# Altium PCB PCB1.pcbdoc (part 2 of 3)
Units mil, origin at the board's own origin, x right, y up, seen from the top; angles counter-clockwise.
Board outline 8664.15 x 6684.89 mil, 2 copper layers (Top Layer, Bottom Layer); 317 components, 306 nets, 1008 pads, 181 vias.
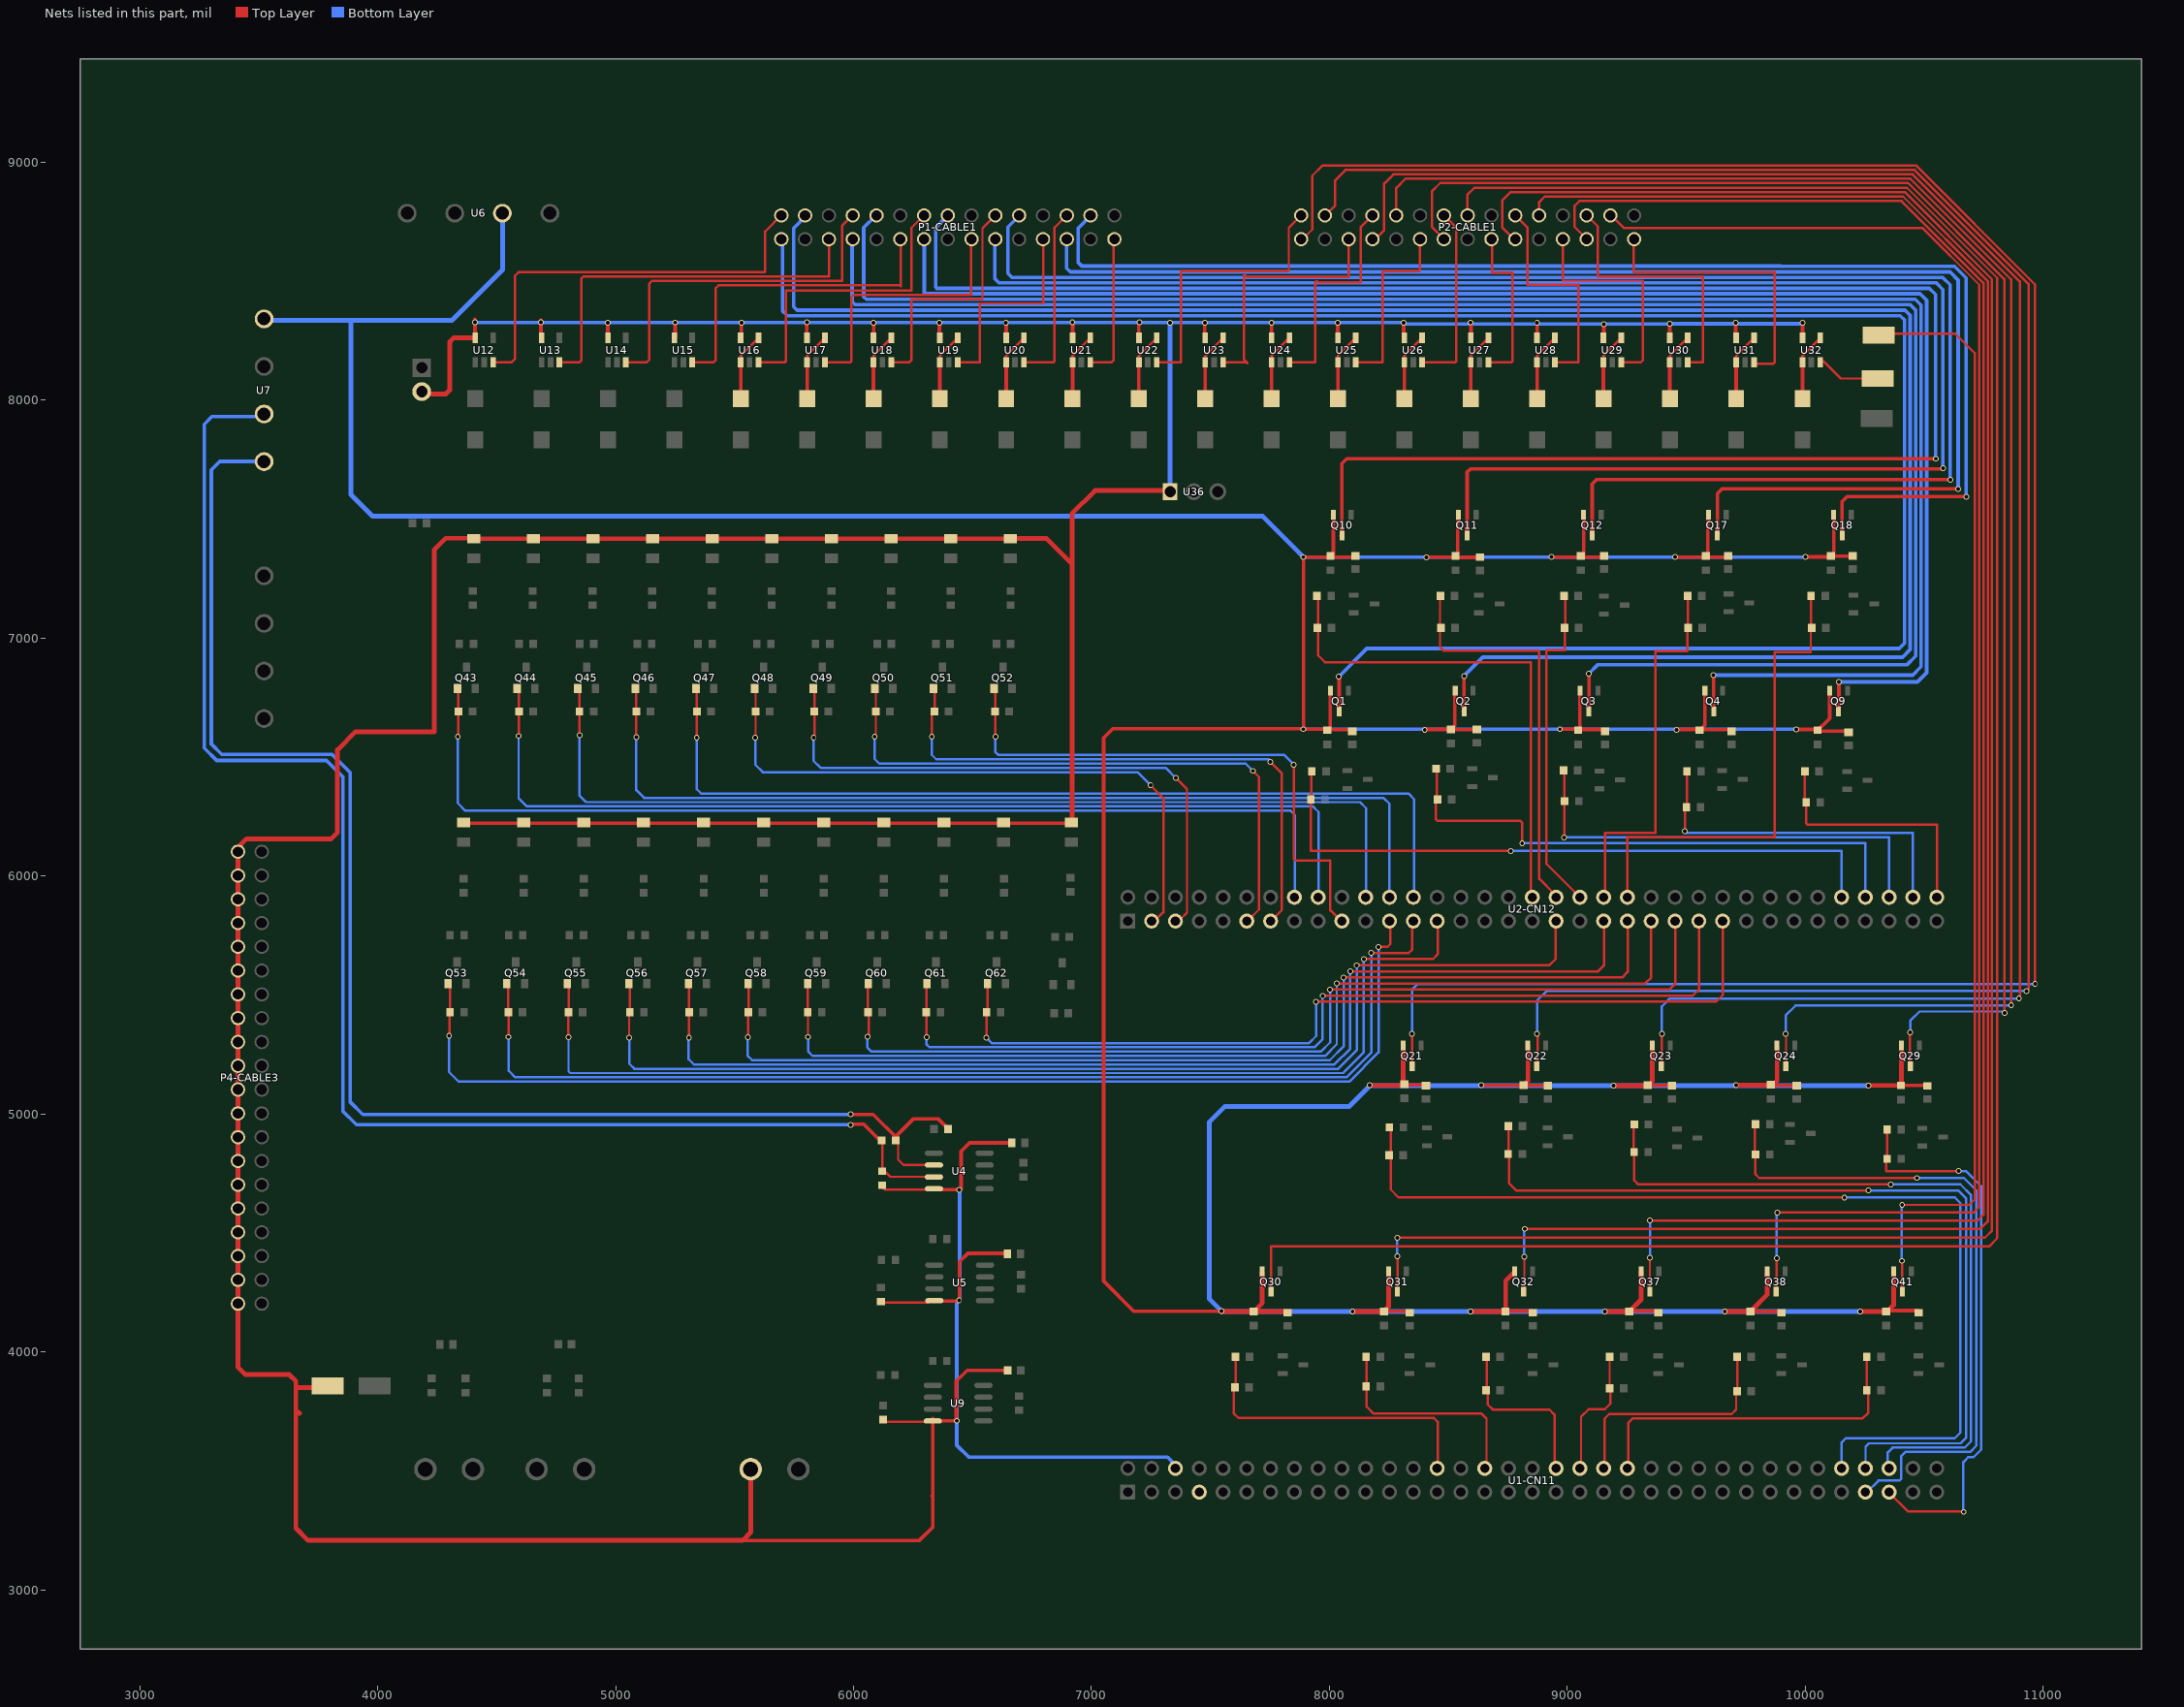
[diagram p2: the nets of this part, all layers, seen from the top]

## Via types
v1: diameter 24.02, hole 16, Top Layer to Bottom Layer, 181 vias

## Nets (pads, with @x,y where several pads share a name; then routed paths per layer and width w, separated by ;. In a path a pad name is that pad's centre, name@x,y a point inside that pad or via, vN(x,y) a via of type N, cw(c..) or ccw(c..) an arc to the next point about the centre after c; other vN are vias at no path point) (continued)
$9N2849: D5.2 U16.1 U16.4 | length 287.2
  Top Layer w10: U16.1@5526.13,8160.48 5526.13,8187.13 5600.93,8261.93 U16.4@5600.93,8262.85
  Top Layer w15: U16.1@5526.13,8160.48 5526.13,8006.71 D5.2@5526.2,8006.64
$9N2931: D6.2 U17.1 U17.4 | length 287.2
  Top Layer w10: U17.1@5805.07,8160.48 5805.07,8187.13 5879.87,8261.93 U17.4@5879.87,8262.85
  Top Layer w15: U17.1@5805.07,8160.48 5805.14,8160.4 D6.2@5805.14,8006.64
$9N3779: D12.2 U23.1 U23.4 | length 287.2
  Top Layer w10: U23.1@7478.69,8160.48 7478.69,8187.13 7553.49,8261.93 U23.4@7553.49,8262.85
  Top Layer w15: U23.1@7478.69,8160.48 7478.69,8006.71 D12.2@7478.76,8006.64
$9N3789: D11.2 U22.1 U22.4 | length 287.2
  Top Layer w10: U22.1@7199.75,8160.48 7199.75,8188.05 U22.4@7274.55,8262.85
  Top Layer w15: U22.1@7199.75,8160.48 7199.75,8006.71 D11.2@7199.83,8006.64
$9N3799: D10.2 U21.1 U21.4 | length 287.2
  Top Layer w10: U21.1@6920.82,8160.48 6920.82,8188.05 U21.4@6995.62,8262.85
  Top Layer w15: U21.1@6920.82,8160.48 6920.82,8006.71 D10.2@6920.89,8006.64
$9N3809: D9.2 U20.1 U20.4 | length 287.2
  Top Layer w10: U20.1@6641.88,8160.48 6641.88,8187.13 6716.68,8261.93 U20.4@6716.68,8262.85
  Top Layer w15: U20.1@6641.88,8160.48 6641.88,8006.71 D9.2@6641.95,8006.64
$9N3819: D8.2 U19.1 U19.4 | length 287.2
  Top Layer w10: U19.1@6362.94,8160.48 6362.94,8187.13 6437.74,8261.93 U19.4@6437.74,8262.85
  Top Layer w15: U19.1@6362.94,8160.48 6362.94,8006.71 D8.2@6363.02,8006.64
$9N3829: D7.2 U18.1 U18.4 | length 287.2
  Top Layer w10: U18.1@6084,8160.48 6084,8187.13 6158.8,8261.93 U18.4@6158.8,8262.85
  Top Layer w15: U18.1@6084,8160.48 6084,8006.71 D7.2@6084.08,8006.64
$10N643: D18.2 U29.1 U29.4 | length 287.2
  Top Layer w10: U29.1@9152.31,8160.48 9152.31,8188.05 U29.4@9227.11,8262.85
  Top Layer w15: U29.1@9152.31,8160.48 9152.31,8006.71 D18.2@9152.39,8006.64
$10N647: D17.2 U28.1 U28.4 | length 287.2
  Top Layer w10: U28.1@8873.38,8160.48 8873.38,8187.13 8948.18,8261.93 U28.4@8948.18,8262.85
  Top Layer w15: U28.1@8873.38,8160.48 8873.38,8006.71 D17.2@8873.45,8006.64
$10N651: D16.2 U27.1 U27.4 | length 287.2
  Top Layer w10: U27.1@8594.44,8160.48 8594.44,8188.05 U27.4@8669.24,8262.85
  Top Layer w15: U27.1@8594.44,8160.48 8594.44,8006.71 D16.2@8594.51,8006.64
$10N655: D15.2 U26.1 U26.4 | length 287.2
  Top Layer w10: U26.1@8315.5,8160.48 8315.5,8188.05 U26.4@8390.3,8262.85
  Top Layer w15: U26.1@8315.5,8160.48 8315.58,8160.4 D15.2@8315.58,8006.64
$10N659: D14.2 U25.1 U25.4 | length 287.2
  Top Layer w10: U25.1@8036.56,8160.48 8036.56,8188.05 U25.4@8111.36,8262.85
  Top Layer w15: U25.1@8036.56,8160.48 8036.64,8160.4 D14.2@8036.64,8006.64
$10N663: D13.2 U24.1 U24.4 | length 287.2
  Top Layer w10: U24.1@7757.63,8160.48 7757.63,8188.05 U24.4@7832.43,8262.85
  Top Layer w15: U24.1@7757.63,8160.48 7757.7,8160.4 D13.2@7757.7,8006.64
$10N673: D21.2 U32.1 U32.4 | length 287.2
  Top Layer w10: U32.1@9989.12,8160.48 9989.12,8187.13 10063.92,8261.93 U32.4@10063.92,8262.85
  Top Layer w15: U32.1@9989.12,8160.48 9989.12,8006.71 D21.2@9989.2,8006.64
$10N677: D20.2 U31.1 U31.4 | length 287.2
  Top Layer w10: U31.1@9710.19,8160.48 9710.19,8187.13 9784.99,8261.93 U31.4@9784.99,8262.85
  Top Layer w15: U31.1@9710.19,8160.48 9710.19,8006.71 D20.2@9710.26,8006.64
$10N681: D19.2 U30.1 U30.4 | length 287.2
  Top Layer w10: U30.1@9431.25,8160.48 9431.25,8188.05 U30.4@9506.05,8262.85
  Top Layer w15: U30.1@9431.25,8160.48 9431.25,8006.71 D19.2@9431.32,8006.64
+5V: C22.1 C23.1 C24.1 CN4.1 LED1.1 LED2.1 LED3.1 LED4.1 LED5.1 LED6.1 LED7.1 LED8.1 LED9.1 LED10.1 LED11.1 LED12.1 LED13.1 LED14.1 LED15.1 LED16.1 LED17.1 LED18.1 LED19.1 LED20.1 LED21.1 P4-CABLE3.1 P4-CABLE3.3 P4-CABLE3.5 P4-CABLE3.7 P4-CABLE3.9 P4-CABLE3.11 P4-CABLE3.13 P4-CABLE3.15 P4-CABLE3.17 P4-CABLE3.19 P4-CABLE3.21 P4-CABLE3.23 P4-CABLE3.25 P4-CABLE3.27 P4-CABLE3.29 P4-CABLE3.31 P4-CABLE3.33 P4-CABLE3.35 P4-CABLE3.37 P4-CABLE3.39 R127.2 R128.2 R135.2 U1-CN11.6 U3.1 U4.8 U5.8 U9.8 U12.5 U13.5 U14.5 U15.5 U16.5 U17.5 U18.5 U19.5 U20.5 U21.5 U22.5 U23.5 U24.5 U25.5 U26.5 U27.5 U28.5 U29.5 U30.5 U31.5 U32.5 U33.2 U36.1 | length 27940.9
  Top Layer w10: R128.2@6112.68,4207.73 6316.98,4207.73 U5.8@6322.09,4212.84 ; R135.2@6122.56,3705.82 6323.67,3705.82 U9.8@6331.33,3713.48 ; R127.2@6124.77,4689.2 6131.79,4682.17 6339.38,4682.17 U4.8@6346.3,4682.31
  Top Layer w15: LED11.1@4357.05,6228.39 4362.71,6222.72 LED21.1@6919.04,6222.72 ; 4408.55,8340.28 4409.19,8339.64 U12.5@4409.19,8260.19 ; U13.5@4686.01,8261.47 v1@4686.01,8335.8 ; LED3.1@4905.51,7418.36 LED3.1@4906.66,7419.51 ; U14.5@4967.31,8263.39 v1@4967.31,8328.75 ; LED4.1@5156.04,7418.36 LED4.1@5157.53,7419.85 ; v1@5249.25,8327.47 5250.54,8326.19 U15.5@5250.54,8262.75 ; LED5.1@5406.56,7418.36 LED5.1@5411.28,7423.08 ; U16.5@5526.07,8265.95 5528.64,8268.52 v1@5528.64,8323.62 ; 5534.4,3207.72 6277.76,3207.72 6333.01,3262.97 6333.01,3393.94 ; v1@5802.89,8317.22 5804.17,8315.93 U17.5@5804.17,8264.67 ; U18.5@6084.19,8263.39 6084.19,8315.29 v1@6086.12,8317.22 ; 6330.57,3393.94 6333.01,3393.94 ; U9.8@6333.01,3719.3 6333.01,3393.94 ; U9.8@6336.78,3710.39 6432.54,3710.39 6432.54,3877.03 6478.19,3922.68 C24.1@6641.31,3922.68 ; U4.8@6339.38,4682.17 U4.8@6339.38,4683.15 ; U5.8@6340.17,4212.83 6341.02,4213.69 v1@6444.66,4213.69 ; U4.8@6341.53,4682.31 6346.3,4682.31 6450.06,4682.31 6452.61,4684.86 6452.61,4843.51 6488.05,4878.95 C22.1@6664.58,4878.95 ; U19.5@6361.01,8262.75 6361.01,8309.53 6363.58,8312.09 ; v1@6443.57,4213.78 6445.08,4215.3 6445.08,4378.19 6481.05,4414.16 6640.23,4414.16 C23.1@6644.06,4410.32 ; v1@6640.69,8327.75 6641.68,8326.76 U20.5@6641.68,8262.75 ; U21.5@6921.06,8263.39 6921.06,8311.45 6923.62,8314.01 ; U22.5@7199.8,8263.39 7199.8,8315.29 v1@7201.72,8317.22 ; U23.5@7475.98,8261.47 7475.98,8322.34 v1@7477.9,8324.26 ; U24.5@7757.92,8260.83 7757.92,8320.42 v1@7758.56,8321.06 ; U25.5@8035.38,8263.39 8035.38,8315.29 v1@8039.86,8319.78 ; U26.5@8312.84,8265.31 v1@8312.84,8319.78 ; U27.5@8595.42,8262.75 8595.42,8318.5 v1@8597.35,8320.42 ; v1@8872.88,8319.78 8874.16,8318.5 U28.5@8874.16,8264.03 ; U29.5@9153.54,8263.39 9153.8,8263.64 9153.8,8318.89 v1@9153.54,8319.14 ; v1@9430.15,8317 9431,8316.15 U30.5@9431,8262.11 ; U31.5@9708.46,8265.31 9708.46,8320.42 v1@9709.1,8321.06 ; v1@9989.01,8322.46 9989.01,8264.15 U32.5@9989.77,8263.39
  Top Layer w20: P4-CABLE3.1@3412.35,6102 3412.35,3936.07 3443.84,3904.57 3628.88,3904.57 3656.44,3877.01 3656.44,3849.59 ; P4-CABLE3.1@3412.8,6099.44 3413.45,6100.08 3413.45,6121.3 3448.6,6156.46 3804.33,6156.46 3830.85,6182.98 3830.85,6530.56 3907.38,6607.09 4237.28,6607.09 4237.28,7371.71 4285.76,7420.19 LED1.1@4402.64,7420.19 ; 3667.07,3746.51 3671,3742.57 ; CN4.1@3790.3,3857.33 3782.56,3849.59 3656.44,3849.59 ; U33.2@4183.36,8026.42 4286.3,8026.42 4303.02,8043.14 4303.02,8245.86 4319.23,8262.08 U12.5@4404.72,8262.08 ; LED1.1@4400.54,7422.29 LED1.1@4402.64,7420.19 ; U3.1@5568.25,3506.93 5568.25,3241.58 5534.4,3207.72 3707.62,3207.72 3656.44,3258.9 3656.44,3727.41 3656.44,3849.59 ; LED10.1@6654.41,7419.88 6655.45,7418.84 6812.26,7418.84 6918.73,7312.37 ; LED10.1@6659.19,7418.36 LED9.1@6408.66,7418.36 LED8.1@6158.14,7418.36 LED7.1@5907.61,7418.36 LED6.1@5657.09,7418.36 LED5.1@5406.56,7418.36 LED4.1@5156.04,7418.36 LED3.1@4905.51,7418.36 LED2.1@4654.99,7418.36 LED1.1@4404.46,7418.36 LED1.1@4402.64,7420.19 ; LED21.1@6922.53,6222.08 6919.03,6225.59 6919.03,7312.08 ; U36.1@7327.32,7620.59 7015.61,7620.59 6918.73,7523.71 6918.73,7312.37 ; 6918.73,7312.37 6919.03,7312.08 ; 6918.73,7312.37 6919.03,7312.08
  Bottom Layer w15: v1@4408.63,8328.43 4410.55,8326.51 v1(4966.64,8326.51) v1(6084.6,8326.51) v1(6360.99,8326.51) v1(6640.79,8326.51) v1(8035.57,8326.51) v1(8312.81,8326.51) 8318.48,8320.84 9429.23,8320.84 v1(9430.34,8321.95) 9984.65,8321.95 v1(9989.21,8326.51) ; v1@6446.44,4679.39 6446.44,4219.89 v1(6443.57,4217.02) 6434.46,4207.91 v1(6434.46,3710.39) 6434.46,3607.66 6484.86,3557.25 7320.03,3557.25 7349.26,3528.02 U1-CN11.6@7349.26,3512.25
  Bottom Layer w20: v1(7331.35,8325.78) 7331.35,7623.82 U36.1@7342.85,7612.33
  other v1: 6444.37,4681.36 9154.78,8319.77 5529.25,8325.65 7476.8,8326.08 7757.47,8325.65 8873.71,8326.08 9708.86,8325.65 4686.41,8327.36 5250.72,8326.93 5803.93,8327.36 8594.33,8326.93 4409.59,8327.79 6920.18,8328.22 7202.12,8327.79
AM1-: C1.1 C2.1 C3.1 C4.1 C5.1 C6.1 C7.1 C8.1 C9.1 C10.1 C11.1 C12.1 C13.1 C14.1 C15.1 C16.1 C17.1 C18.1 C19.1 C20.1 C21.1 Q1.2 Q2.2 Q3.2 Q4.2 Q9.2 Q10.2 Q11.2 Q12.2 Q17.2 Q18.2 Q21.2 Q22.2 Q23.2 Q24.2 Q29.2 Q30.2 Q31.2 Q32.2 Q37.2 Q38.2 Q41.2 R1.2 R2.2 R3.2 R4.2 R13.2 R14.2 R15.2 R16.2 R25.2 R26.2 R31.2 R32.2 R33.2 R34.2 R43.2 R44.2 R45.2 R46.2 R55.2 R56.2 R61.2 U6.3 U7.4 | length 29666.8
  Top Layer w10: R44.2@7676.44,4163.63 R44.2@7682.21,4169.39 ; C11.1@8419.23,5126.41 C11.1@8421.15,5124.49 ; R2.2@8509.36,6614.09 8516.96,6621.7 R2.2@8515.94,6621.7 ; R3.2@9045.17,6608.18 R3.2@9053.71,6616.73 ; R16.2@9051.67,7345.37 9061.28,7345.37 R16.2@9057.44,7341.52 ; R4.2@9554.71,6610.89 R4.2@9560.48,6616.65 ; R56.2@9770.15,4170.3 R56.2@9773.79,4173.95 ; R34.2@9851.42,5123.08 R34.2@9860.39,5123.08 ; R61.2@10336.6,4174.15 R61.2@10348.77,4174.15 ; R43.2@10405.25,5120.28 10405.25,5116.51 R43.2@10408.54,5113.23 ; R34.2@9860.39,5123.08 9862.96,5120.52 9865.52,5123.08 R34.2@9860.39,5123.08
  Top Layer w15: v1(7547.37,4171.17) 7178.28,4171.17 7051.55,4297.9 7051.55,6580.88 7090.41,6619.74 7889.05,6619.74 v1(7891.12,6617.67) ; v1(7891.62,7340.66) 7891.62,6618.17 v1(7891.12,6617.67) ; v1@7894.01,7340.64 R14.2@8000.38,7340.64 ; R1.2@7979.72,6619.47 7977.92,6617.67 v1(7891.12,6617.67) ; R1.2@8000.48,6615.56 8090.68,6615.56 C1.1@8096.24,6610 ; R1.2@8004.03,6619.1 Q1.2@8004.03,6778.02 ; R14.2@8006.55,7340.85 8112.07,7340.85 C6.1@8113.78,7342.55 ; R14.2@8006.55,7343.41 8017.23,7354.09 Q10.2@8017.23,7513.43 ; R45.2@8238.57,4170.35 8332.76,4170.35 C17.1@8337.25,4165.87 ; R31.2@8309,5122.18 8402.21,5122.18 C11.1@8402.85,5121.54 ; v1@8404.17,6616.57 8510.81,6616.57 8515.94,6621.7 8527.25,6633.01 Q2.2@8527.25,6775.27 ; v1@8414,7340.73 8525.22,7340.73 8540.22,7355.73 Q11.2@8540.22,7517.63 ; R2.2@8516.96,6621.7 8523.23,6615.43 C2.1@8624.63,6615.43 ; R15.2@8533.76,7347.17 8541.02,7339.91 C7.1@8633.29,7339.91 ; v1@8640.86,5120.29 8815.97,5120.29 8912.94,5120.29 C12.1@8916.36,5116.87 ; R46.2@8741.58,4171.48 8849.24,4171.48 C18.1@8856.28,4164.43 ; v1(8934.55,7341.15) 9049.04,7341.15 R16.2@9049.47,7341.58 ; v1@8971.23,6617.18 9045.56,6617.18 R3.2@9046.2,6616.54 ; Q3.2@9053.71,6781.62 9053.71,6616.73 9156.93,6616.73 C3.1@9166.22,6607.43 ; Q12.2@9069.93,7520.3 9069.93,7354.02 9061.28,7345.37 9065.84,7340.81 C8.1@9149.46,7340.81 ; R55.2@9270.55,4172.12 C19.1@9379.16,4172.12 ; R33.2@9343.28,5123.72 9347.11,5119.89 9432.36,5119.89 C13.1@9436.19,5123.72 ; v1(9453.16,7342.01) 9454.01,7341.15 R25.2@9578.33,7341.15 ; v1@9457.59,6613.34 9460.9,6616.65 R4.2@9560.48,6616.65 ; Q4.2@9578.74,6780.05 9578.74,6634.92 R4.2@9560.48,6616.65 ; R25.2@9582.45,7346.85 9591.1,7355.5 Q17.2@9591.1,7518.9 ; R25.2@9593.02,7346.85 9599.43,7340.44 C9.1@9678.25,7340.44 ; C4.1@9692.16,6605.12 9682.16,6615.12 9562.01,6615.12 R4.2@9560.48,6616.65 ; R56.2@9773.99,4169.66 9895.1,4169.66 C20.1@9901.51,4163.25 ; R34.2@9865.52,5123.08 9868.64,5119.96 9965.56,5119.96 C14.1@9969.97,5124.36 ; v1(9963.26,6616.2) 10047.85,6616.2 R13.2@10048.7,6615.35 ; v1(10001.14,7341.58) 10103.66,7341.58 R26.2@10108.79,7346.7 ; R13.2@10048.58,6608.08 10103.05,6662.54 Q9.2@10103.05,6775.32 ; R13.2@10060.66,6609.8 10174.72,6609.8 C5.1@10179.42,6605.1 ; R26.2@10111.1,7348.77 10120.71,7358.38 Q18.2@10120.71,7516.98 ; R26.2@10119.75,7344.93 10204.33,7344.93 C10.1@10209.14,7349.73 ; R61.2@10348.77,4174.15 10475.65,4174.15 C21.1@10484.62,4165.18 ; R43.2@10405.25,5120.28 C15.1@10511.06,5120.28
  Top Layer w20: v1@7548.81,4168.05 7550.16,4169.39 R44.2@7682.21,4169.39 ; Q30.2@7718.09,4334.72 7718.09,4205.28 R44.2@7682.21,4169.39 ; C16.1@7833.43,4167.47 7831.51,4169.39 R44.2@7682.21,4169.39 ; v1@8100.53,4169.01 8226.97,4169.01 8248.8,4190.84 Q31.2@8248.8,4334.09 ; v1@8168.17,5119.29 8168.94,5120.06 R31.2@8307.28,5120.06 ; R31.2@8310.6,5130.97 Q21.2@8310.6,5276.06 ; v1@8593.8,4170.45 8594.99,4169.26 8739.36,4169.26 8741.58,4171.48 8741.58,4298.35 Q32.2@8780.03,4336.8 ; R32.2@8815.97,5120.29 8835.34,5139.66 Q22.2@8835.34,5285.77 ; v1@9160.67,4168.97 9250.05,4168.97 R55.2@9254.9,4173.81 ; v1@9199.22,5118.6 9338.16,5118.6 9343.28,5123.72 9358.02,5138.46 Q23.2@9358.02,5287.12 ; R55.2@9259.66,4169.02 9311.35,4220.71 Q37.2@9311.35,4339.9 ; v1@9659.62,4169.08 9767.27,4169.08 9773.79,4173.95 9841.27,4241.43 Q38.2@9841.27,4331.14 ; v1@9714.02,5121.25 9714.59,5120.68 9857.99,5120.68 R34.2@9860.39,5123.08 ; R34.2@9865.52,5123.08 9882.18,5139.74 Q24.2@9882.18,5281.99 ; v1@10231.45,4169.01 10232.4,4169.96 10336.3,4169.96 10340.44,4165.82 10348.77,4174.15 10371.56,4196.93 Q41.2@10371.56,4335.91 ; v1@10264.61,5119.97 10264.92,5120.28 10405.25,5120.28 Q29.2@10405.25,5281.55
  Bottom Layer w15: v1(7891.12,6617.67) 9961.22,6617.67 v1@9965.01,6613.88 ; v1(7891.62,7340.66) 10002.47,7340.66 v1@10003.02,7341.21
  Bottom Layer w20: U7.4@3543.78,8344.72 3552.43,8336.07 3887.64,8336.07 ; U6.3@4527.2,8778.4 4525.38,8776.57 4525.38,8549.05 4312.4,8336.07 3887.64,8336.07 ; v1(7891.62,7340.66) 7720.18,7512.1 3979.44,7512.1 3887.64,7603.9 3887.64,8336.07 ; v1(8169.43,5121.39) v1@8167.85,5119.8 ; v1(10232.38,4169.82) 9662.18,4169.82 v1(8594.05,4169.78) 7548.72,4169.82 v1(7547.37,4171.17) 7495.03,4223.51 7495.03,4965.92 7561.45,5032.33 8084.23,5032.33 8169.77,5117.88 v1@8167.85,5119.8 ; v1(10266.44,5119.8) v1@8167.85,5119.8
  other v1: 8097.56,4169.46 9157.97,4169.97 9662.18,4169.88 9195.08,5119.05 8639.02,5120.54 9709.31,5121.05 8401.25,6615.14 9460.05,6615.17 8969.62,6617.49 8408.24,7340.24
AM1-A: R131.1 R133.2 U4.6 U7.1 | length 6291.1
  Top Layer w10: R131.1@6187.73,4893.81 6187.73,4808.26 6210.08,4785.92 6330.74,4785.92 U4.6@6332.02,4784.64
  Top Layer w15: v1@5982.88,4998.24 6082.67,4998.24 6185.18,4895.73 6185.18,4912.97 6251.26,4979.05 6356.6,4979.05 R133.2@6395.86,4939.78
  Bottom Layer w15: U7.1@3521.35,7743.41 3336.73,7743.41 3300.61,7707.3 3300.61,6555.12 3344.16,6511.57 3807.99,6511.57 3885.19,6434.37 3885.19,5049.88 3937.08,4997.99 5987.01,4997.99 v1@5990.49,5001.47
  other v1: 5987.74,4998.24
AM1-B: R127.1 R131.2 U4.7 U7.2 | length 6341.3
  Top Layer w10: R127.1@6116.86,4758.47 6120.7,4762.3 R131.2@6120.7,4885.52 ; R127.1@6126.44,4765.49 6155.81,4736.12 U4.7@6330.1,4736.12
  Top Layer w15: v1@5985.31,4956.98 6043.56,4956.98 R131.2@6116.36,4884.17
  Bottom Layer w15: U7.2@3535.91,7931.34 3303.29,7931.34 3271.29,7899.34 3271.29,6537.84 3322.84,6486.29 3785.12,6486.29 3853.44,6417.97 3853.44,5012.5 3911.25,4954.69 5986.08,4954.69 v1@5987.75,4956.36
  other v1: 5987.74,4954.55
BOOT0: U1-CN11.7
D1-3.3V: P1-CABLE1.2 U12.3 | length 1770
  Top Layer w10: U12.3@4485.18,8160.48 4563.9,8160.48 4577.7,8174.28 4577.7,8524.32 4591.81,8538.43 5624.95,8538.43 5628.88,8542.37 5628.88,8709.69 P1-CABLE1.2@5696.6,8777.41
D1-5V: P1-CABLE1.1 Q1.3 | length 8966.8
  Top Layer w15: v1(8040.32,6838.32) 8041.27,6837.36 Q1.3@8041.27,6692.76
  Bottom Layer w15: P1-CABLE1.1@5701.16,8674.03 5701.16,8377.15 5722.59,8355.72 10399.91,8355.72 10418.72,8336.92 10418.72,6979.72 10395.74,6956.74 8157.78,6956.74 v1@8043.19,6842.15
D2-3.3V: P1-CABLE1.5 U13.3 | length 1639.7
  Top Layer w10: U13.3@4764.12,8160.48 4848.49,8160.48 4857.23,8169.21 4857.23,8512.58 4865.08,8520.43 5896.6,8520.43 P1-CABLE1.5@5896.6,8677.41
D2-5V: P1-CABLE1.4 Q2.3 | length 8577.3
  Top Layer w15: Q2.3@8563.38,6692.5 8566.78,6695.9 v1@8566.78,6837.64
  Bottom Layer w15: P1-CABLE1.4@5796.37,8771.53 5748.31,8723.47 5748.31,8393.52 5763.11,8378.72 10420.44,8378.72 10441.72,8357.44 10441.72,6952.56 10409.58,6920.43 8645.05,6920.43 v1@8567.56,6842.93
  other v1: 8567.28,6841.25
D3-3.3V: P1-CABLE1.8 U14.3 | length 1530.9
  Top Layer w10: U14.3@5043.06,8160.48 5131.16,8160.48 5140.69,8170.01 5140.69,8489.24 5153.89,8502.43 5951.72,8502.43 5951.72,8732.53 P1-CABLE1.8@5996.6,8777.41
D3-5V: P1-CABLE1.7 Q3.3 | length 7758.1
  Top Layer w15: v1(9091.47,6850.51) 9091.68,6850.3 Q3.3@9091.68,6692.82
  Bottom Layer w15: P1-CABLE1.7@5994.01,8674.93 5994.01,8413.63 6005.92,8401.72 10441.95,8401.72 10464.72,8378.96 10464.72,6925.37 10427.2,6887.85 9127.85,6887.85 v1@9093.95,6853.95
D4-3.3V: P1-CABLE1.11 U15.3 | length 1389.4
  Top Layer w10: U15.3@5321.99,8160.48 5412.33,8160.48 5420.22,8168.36 5420.22,8470.51 5433.03,8483.31 6195.81,8483.31 6199.75,8479.38 6199.75,8674.26 P1-CABLE1.11@6196.6,8677.41
D4-5V: P1-CABLE1.10 Q4.3 | length 7382
  Top Layer w15: Q4.3@9615.81,6690.48 v1@9615.81,6843.31
  Bottom Layer w15: P1-CABLE1.10@6094.61,8777.29 6043.27,8725.95 6043.27,8435.83 6054.37,8424.72 10463.4,8424.72 10487.72,8400.4 10487.72,6879.89 10452.52,6844.7 9617.04,6844.7 v1@9615.96,6843.61
  other v1: 9614.85,6844.27
D5-3.3V: P1-CABLE1.14 U16.3 | length 1278.9
  Top Layer w10: U16.3@5600.93,8160.48 5711.56,8160.48 5715.5,8164.41 5715.5,8461.38 6243.06,8461.38 6243.06,8723.87 P1-CABLE1.14@6296.6,8777.41
D5-5V: P1-CABLE1.13 Q9.3 | length 6534.7
  Top Layer w15: Q9.3@10140.86,6688.5 10141.82,6689.46 10141.82,6816.65 v1@10143.1,6817.93
  Bottom Layer w15: P1-CABLE1.13@6297.5,8676.16 6297.5,8447.72 10483.67,8447.72 10510.72,8420.67 10510.72,6854.55 10472.42,6816.25 10142.79,6816.25 v1@10141.68,6815.13
  other v1: 10141.51,6816.7
D6-3.3V: P1-CABLE1.17 U17.3 | length 1125.4
  Top Layer w10: U17.3@5879.87,8160.48 5987.15,8160.48 5991.09,8164.42 5991.09,8434.76 5999.71,8443.38 6495.03,8443.38 6495.03,8675.83 P1-CABLE1.17@6496.6,8677.41
D6-5V: P1-CABLE1.16 Q10.3 | length 8041.7
  Top Layer w15: Q10.3@8048.57,7430.06 8052.85,7434.33 8052.85,7733.91 8072.81,7753.88 10548.44,7753.88 v1(10548.79,7754.23)
  Bottom Layer w15: P1-CABLE1.16@6393.6,8779.06 6393.6,8773.8 6345.32,8725.52 6345.32,8475.83 6350.43,8470.72 10522.26,8470.72 10548.14,8444.85 10548.14,7753.71 v1@10546.9,7752.47
D7-3.3V: P1-CABLE1.20 U18.3 | length 1018.3
  Top Layer w10: U18.3@6158.8,8160.48 6235.18,8160.48 6243.06,8168.35 6243.06,8425.38 6542.27,8425.38 6542.27,8723.08 P1-CABLE1.20@6596.6,8777.41
D7-5V: P1-CABLE1.19 Q11.3 | length 7197.7
  Top Layer w15: Q11.3@8579.85,7431.01 8579.85,7698.05 8592.76,7710.96 10576.32,7710.96 v1(10579.55,7714.18)
  Bottom Layer w15: P1-CABLE1.19@6593.81,8677.57 6593.81,8511.07 6611.15,8493.72 10551.69,8493.72 10579.54,8465.87 v1@10579.54,7712.56
D8-3.3V: P1-CABLE1.23 U19.3 | length 878
  Top Layer w10: U19.3@6437.74,8160.48 6530.46,8160.48 6530.46,8407.38 6798.18,8407.38 6798.18,8675.83 P1-CABLE1.23@6796.6,8677.41
D8-5V: P1-CABLE1.22 Q12.3 | length 6769.8
  Top Layer w15: 9105.37,7452.64 9105.37,7648.86 9122.63,7666.12 v1(10609.88,7666.12)
  Bottom Layer w15: P1-CABLE1.22@6695.81,8774.73 6649.04,8727.95 6649.04,8534.03 6666.34,8516.72 10577.87,8516.72 10609.19,8485.41 10609.19,7667.57 v1@10611.8,7664.95
D9-3.3V: P1-CABLE1.26 U20.3 | length 764.6
  Top Layer w10: U20.3@6716.68,8160.48 6841.48,8160.48 6845.42,8164.42 6845.42,8726.23 P1-CABLE1.26@6896.6,8777.41
D9-5V: P1-CABLE1.25 Q17.3 | length 5957.6
  Top Layer w15: Q17.3@9635.98,7438.51 9631.66,7442.84 9631.66,7608.19 9651.14,7627.68 v1(10642.98,7627.68)
  Bottom Layer w15: P1-CABLE1.25@6896.16,8675.14 6896.16,8555.13 6911.57,8539.72 10609.31,8539.72 10643.61,8505.42 v1@10643.61,7626.73
D10-3.3V: P1-CABLE1.29 U21.3 | length 611.5
  Top Layer w10: U21.3@6995.62,8160.48 7085.57,8160.48 7093.45,8168.35 7093.45,8674.26 P1-CABLE1.29@7096.6,8677.41
D10-5V: P1-CABLE1.28 Q18.3 | length 5558.2
  Top Layer w15: Q18.3@10155.01,7442.84 10155.01,7574.4 10176.24,7595.62 10677.1,7595.62 v1(10677.73,7595)
  Bottom Layer w15: P1-CABLE1.28@6996.35,8775.55 6945.09,8724.29 6945.09,8578.7 6959.7,8564.09 9896.54,8564.09 9897.91,8562.72 10627.94,8562.72 10676.54,8514.12 10676.54,7595.77 v1@10676.38,7595.6
D11-3.3V: P2-CABLE1.2 U22.3 | length 1191.3
  Top Layer w10: U22.3@7274.55,8160.48 7376.92,8160.48 7376.92,8542.37 7825.74,8542.37 7829.67,8546.31 7829.67,8725.45 P2-CABLE1.2@7881.63,8777.4
D11-5V: P2-CABLE1.1 Q21.3 | length 9437.4
  Top Layer w10: P2-CABLE1.1@7886.45,8675.55 7928.74,8717.84 7928.74,8944.17 7971.89,8987.32 10466,8987.32 10966.38,8486.93 v1@10966.38,5546.51 ; Q21.3@8346.59,5200.15 8347.87,5201.43 v1@8347.87,5333.43
  Bottom Layer w10: v1(8347.39,5336.96) 8347.39,5522.15 8371.75,5546.51 v1(10966.32,5546.51)
D12-3.3V: P2-CABLE1.5 U23.3 | length 1076.1
  Top Layer w10: U23.3@7553.49,8160.48 7652.51,8160.48 ; 7656.44,8156.54 7652.51,8160.48 ; P2-CABLE1.5@8078.73,8676.02 P2-CABLE1.5@8079.59,8676.02 ; P2-CABLE1.5@8081.63,8677.4 8081.64,8518.75 7652.51,8518.75 7646.88,8524.37 7640.7,8524.37 7640.7,8172.29 7652.51,8160.48
D12-5V: P2-CABLE1.4 Q22.3 | length 8624.2
  Top Layer w10: P2-CABLE1.4@7977.49,8779.86 7985.61,8779.86 8024.63,8818.89 8024.63,8924.35 8067.97,8967.7 10460.16,8967.7 10938.81,8489.05 10938.81,5525.74 v1@10931.29,5518.23 ; Q22.3@8870.43,5200.79 8876.2,5206.56 v1@8876.2,5335.35
  Bottom Layer w10: v1(8873.47,5336.31) 8873.47,5476.6 8915.01,5518.13 v1@10930.15,5518.13
  other v1: 10930.15,5516.22
D13-3.3V: P2-CABLE1.8 U24.3 | length 942.2
  Top Layer w10: U24.3@7832.43,8160.48 7939.91,8160.48 7939.91,8495.13 7945.53,8500.75 7947.78,8500.75 7953.4,8495.13 8132.82,8495.13 8132.82,8728.6 P2-CABLE1.8@8181.63,8777.4
D13-5V: P2-CABLE1.7 Q23.3 | length 7903.2
  Top Layer w10: P2-CABLE1.7@8191.22,8675.3 8230.62,8714.71 8230.62,8910.78 8269.54,8949.7 10452.38,8949.7 10902.64,8499.44 10902.64,5489.23 v1@10898.89,5485.48 ; Q23.3@9397.15,5203.67 v1@9397.15,5335.35
  Bottom Layer w10: v1(9398.28,5336.96) 9398.28,5452.09 9431.67,5485.48 v1@10898.89,5485.48
  other v1: 10898.89,5485.92
D14-3.3V: P2-CABLE1.11 U25.3 | length 782.1
  Top Layer w10: U25.3@8111.36,8160.48 8223.37,8160.48 8223.37,8538.43 8227.31,8542.37 8376.92,8542.37 8381.63,8547.08 P2-CABLE1.11@8381.63,8677.4
D14-5V: P2-CABLE1.10 Q24.3 | length 7119.3
  Top Layer w10: P2-CABLE1.10@8281.38,8776.27 8281.38,8892.65 8320.43,8931.7 10442.05,8931.7 10866.23,8507.52 v1@10866.23,5455.28 ; v1@9919.07,5337.28 9920.03,5336.31 Q24.3@9920.03,5205.6
  Bottom Layer w10: v1(9918.59,5336.96) 9918.59,5414.24 9959.75,5455.39 v1@10866.14,5455.39
  other v1: 10866.33,5457.13
D15-3.3V: P2-CABLE1.14 U26.3 | length 780.6
  Top Layer w10: U26.3@8390.3,8160.48 8530.46,8160.48 8534.4,8164.42 8534.4,8724.64 P2-CABLE1.14@8481.63,8777.4
D15-5V: P2-CABLE1.13 Q29.3 | length 6499
  Top Layer w10: P2-CABLE1.13@8482.6,8677.3 8431.34,8728.57 8431.34,8878.47 8466.56,8913.7 10433.16,8913.7 10837.49,8509.37 10837.49,5424.99 v1@10839.34,5423.14 ; v1@10439.07,5340.16 10440.03,5339.2 Q29.3@10440.03,5202.71
  Bottom Layer w10: v1(10442.11,5343.36) 10442.11,5391.71 10481.19,5430.79 10833.36,5430.79 v1(10838.82,5425.33)
D16-3.3V: P2-CABLE1.17 U27.3 | length 703.6
  Top Layer w10: U27.3@8669.24,8160.48 8766.68,8160.48 8770.62,8164.42 8770.62,8537.56 8684,8537.56 8684,8675.03 P2-CABLE1.17@8681.63,8677.4
D16-5V: P2-CABLE1.16 Q30.3 | length 9776.4
  Top Layer w10: Q30.3@7756.31,4254.23 7756.31,4443.27 10772.98,4443.27 10807.06,4477.35 10807.06,8514.37 10428.31,8893.12 8609.55,8893.12 8579.6,8863.18 P2-CABLE1.16@8579.6,8774.48
D17-3.3V: P2-CABLE1.20 U28.3 | length 949.1
  Top Layer w10: P2-CABLE1.20@8781.63,8777.4 8833.61,8725.42 8833.61,8484.96 9046.21,8484.96 9046.21,8160.48 U28.3@8948.18,8160.48
D17-5V: P2-CABLE1.19 Q31.3 | length 9168.5
  Top Layer w10: v1@8279.79,4480.27 10756.26,4480.27 10785.68,4509.69 10785.68,8508.24 10418.8,8875.12 8762.45,8875.12 8726.48,8839.15 8726.48,8727.2 P2-CABLE1.19@8784.15,8669.53 ; Q31.3@8286.4,4248.94 8286.4,4397.92 v1@8290.24,4401.77
  Bottom Layer w10: v1(8285.75,4402.12) 8285.75,4479.47 v1(8286.11,4479.83)
D18-3.3V: P2-CABLE1.23 U29.3 | length 939.3
  Top Layer w10: P2-CABLE1.23@8981.63,8677.4 8981.63,8502.96 9317.86,8502.96 9317.86,8168.35 9309.98,8160.48 U29.3@9227.11,8160.48
D18-5V: P2-CABLE1.22 Q32.3 | length 8276
  Top Layer w10: v1@8818.89,4396.96 8819.85,4396 Q32.3@8819.85,4252.78 ; v1@8821.11,4517.36 10736.71,4517.36 10767.68,4548.33 10767.68,8500.78 10411.86,8856.6 8905.38,8856.6 8882.49,8833.72 P2-CABLE1.22@8882.49,8774.58
  Bottom Layer w10: v1(8819.74,4399.42) 8819.74,4515.57 v1(8821.31,4517.14)
D19-3.3V: P2-CABLE1.26 U30.3 | length 1141.2
  Top Layer w10: P2-CABLE1.26@9081.63,8777.4 9128.89,8730.15 9128.89,8520.96 9569.83,8520.96 9569.83,8160.48 U30.3@9506.05,8160.48
D19-5V: P2-CABLE1.25 Q37.3 | length 7666.3
  Top Layer w10: P2-CABLE1.25@9085.83,8674.14 9030.72,8729.25 9030.72,8817.27 9051.24,8837.79 10405.21,8837.79 10749.68,8493.33 10749.68,4576.57 10725.7,4552.59 9351.98,4552.59 v1@9348.13,4548.75 ; Q37.3@9347.53,4253.75 9347.53,4392.15 v1@9351.38,4396
  Bottom Layer w10: v1(9348.17,4396) v1@9348.17,4552.5
  other v1: 9348.14,4552.53
D20-3.3V: P2-CABLE1.29 U31.3 | length 1204.4
  Top Layer w10: P2-CABLE1.29@9279.38,8685.78 9279.38,8538.96 9871.46,8538.96 9871.46,8159.06 9866.65,8154.25 U31.3@9787.84,8154.25
D20-5V: P2-CABLE1.28 Q38.3 | length 6747.9
  Top Layer w10: P2-CABLE1.28@9178.97,8774.2 9188.86,8774.2 9238.16,8724.89 10492.66,8724.89 10731.68,8485.87 10731.68,4609.16 10708.48,4585.96 9881.37,4585.96 v1@9878.53,4588.8 ; v1@9879.06,4394.08 9880.02,4393.12 Q38.3@9880.02,4251.82
  Bottom Layer w10: v1(9880.66,4393.44) 9881.09,4393.86 9881.09,4583.5 v1(9882.68,4585.09)
D21-3.3V: CN2.1 U32.3 | length 245.6
  Top Layer w10: 10077.49,8164.65 10150.54,8091.6 CN2.1@10292.8,8091.6
D21-5V: CN1.1 Q41.3 | length 4687
  Top Layer w10: CN1.1@10295.48,8279.65 10631.9,8279.65 10713.68,8197.87 10713.68,4641.23 10690.48,4618.02 10413.64,4618.02 v1@10407.31,4624.35 ; Q41.3@10407.71,4253.75 10407.71,4376.78 v1@10409.63,4378.7
  Bottom Layer w10: v1(10406.75,4382.54) v1@10406.75,4616.51
  other v1: 10407.95,4617.72
DIG1: R5.2 R9.2 U2-CN12.62 | length 2745.4
  Top Layer w10: R5.2@7920.66,6432.29 7924.08,6428.87 R9.2@7924.08,6322.08 ; R9.2@7922.17,6317.93 7922.17,6106 8760.44,6106 v1@8760.81,6106.37
  Bottom Layer w10: v1(8763.44,6105.78) 10153.35,6105.78 10153.75,6105.38 10153.75,5918.28 U2-CN12.62@10149.9,5914.43
DIG2: R6.2 R10.2 U2-CN12.64 | length 2343.6
  Top Layer w10: R6.2@8446,6447.08 8451.76,6441.32 R10.2@8451.76,6313.48 ; R10.2@8448.34,6322.25 8448.34,6238.63 8454.1,6232.86 8801.18,6232.86 8811.18,6222.86 8811.18,6137.9 v1@8809.28,6136
  Bottom Layer w10: v1(8810.73,6138.53) 8811.33,6137.93 10253.77,6137.93 U2-CN12.64@10253.77,5914.23
DIG3: R7.2 R11.2 U2-CN12.66 | length 1906.5
  Top Layer w10: R11.2@8975.88,6316.37 R11.2@8987.41,6327.9 ; v1@8984.48,6161.2 8987.41,6164.14 R11.2@8987.41,6327.9 ; R7.2@8987.41,6446.45 R11.2@8987.41,6327.9
  Bottom Layer w10: v1(8987.03,6162.94) 8987.11,6163.02 10352.49,6163.02 10352.49,5933.23 U2-CN12.66@10358.47,5927.25
DIG4: R8.2 R12.2 U2-CN12.68 | length 1473.4
  Top Layer w10: v1@9494.84,6186.68 9495.27,6187.1 9495.27,6277.18 R12.2@9494.84,6277.61 ; R12.2@9503.77,6290.82 9503.77,6434.99 R8.2@9510.49,6441.72
  Bottom Layer w10: v1(9494.52,6188.03) 9500.34,6182.21 10452.17,6182.21 10452.17,5926.06 U2-CN12.68@10443.52,5917.41
DIG5: R17.2 R21.2 U2-CN12.70 | length 1087.9
  Top Layer w10: R17.2@9999.24,6446.6 9999.24,6308.83 R21.2@10002.44,6305.63 ; R21.2@10005.22,6312.21 10005.22,6221.38 10009.55,6217.05 10554.54,6217.05 10554.54,5916.45 U2-CN12.70@10556.7,5914.28
DIG6: R18.2 R22.2 U2-CN12.36 | length 2124.3
  Top Layer w10: R22.2@7948.21,7041.44 7953.33,7046.56 R18.2@7953.33,7169.59 ; R22.2@7953.01,7038.4 7953.01,6927.59 7982.15,6898.45 8847.86,6898.45 8847.86,5928.24 U2-CN12.36@8852.19,5923.92
DIG7: R19.2 R23.2 U2-CN12.38 | length 1706.3
  Top Layer w10: R23.2@8458.58,7046.33 R23.2@8465.32,7039.6 ; R23.2@8466.6,7032.47 R23.2@8465.32,7033.75 ; R19.2@8466.6,7183.05 8465.32,7181.77 R23.2@8465.32,7039.6 ; U2-CN12.38@8947.34,5923.92 8882.46,5988.8 8882.46,6948.05 8480.14,6948.05 8465.32,6962.87 R23.2@8465.32,7033.75 ; R23.2@8465.32,7033.75 R23.2@8465.32,7039.6
DIG8: R20.2 R24.2 U2-CN12.40 | length 1397.1
  Top Layer w10: R24.2@8990.59,7037.68 8990.59,6949.08 8913.02,6949.08 8913.02,6051.23 U2-CN12.40@9051.15,5913.1 ; R20.2@8991.19,7178.99 8991.61,7178.56 R24.2@8991.61,7041.44
DIG9: R27.2 R29.2 U2-CN12.42 | length 1603.6
  Top Layer w10: U2-CN12.42@9157,5910.94 9159.16,5913.1 9159.37,6181.02 9371.2,6181.02 9371.2,6946.31 9506.16,6946.31 R29.2@9506.16,7034.85 ; R29.2@9507.66,7043.15 9507.66,7172.16 R27.2@9509.79,7174.29
DIG10: R28.2 R30.2 U2-CN12.44 | length 2038.2
  Top Layer w10: U2-CN12.44@9253,5908.54 9253,6163.02 9872.26,6163.02 9872.26,6942.18 10023.86,6942.18 R30.2@10023.86,7047.05 ; R30.2@10025.84,7041.22 R28.2@10025.84,7170.02
DIG11: R35.2 R39.2 U1-CN11.62 | length 4272.1
  Top Layer w10: R35.2@8258.39,4939.31 8258.39,4682 8290.72,4649.68 v1@10166.82,4649.68
  Bottom Layer w10: U1-CN11.62@10155.05,3504.53 10153.77,3505.81 10153.77,3619.32 10171.32,3636.87 10628.49,3636.87 10652.4,3660.78 10652.4,4626 10629.12,4649.28 v1(10165.37,4649.28)
DIG12: R36.2 R40.2 U1-CN11.64 | length 3737.1
  Top Layer w10: R36.2@8746.07,4953.3 8753.11,4946.25 R40.2@8753.11,4826.42 ; R40.2@8747.74,4825.66 8756.39,4817.01 8756.39,4708.3 8785.9,4678.78 10265.07,4678.78 v1@10267.63,4676.23
  Bottom Layer w10: U1-CN11.64@10247.3,3505.48 U1-CN11.64@10254.14,3505.48 ; U1-CN11.64@10255.16,3515.02 10254.2,3515.98 10254.2,3600.67 10269.16,3615.63 10653.08,3615.63 10677.68,3640.23 10677.68,4644.26 10643.42,4678.52 v1(10266.79,4678.52)
DIG13: R37.2 R41.2 U1-CN11.66 | length 3165.5
  Top Layer w10: R41.2@9274.9,4837.12 9278.74,4840.96 R37.2@9278.74,4958.87 ; R41.2@9281.91,4836.48 9281.91,4721.04 9298.85,4704.1 v1(10360.75,4704.1)
  Bottom Layer w10: U1-CN11.66@10344.91,3501.32 U1-CN11.66@10344.91,3512.43 ; U1-CN11.66@10347.46,3505.47 10347.46,3577.2 10367.89,3597.63 10670.81,3597.63 10698.11,3624.93 10698.11,4658.69 10652.4,4704.4 v1@10363.17,4704.4
DIG14: R38.2 R42.2 U1-CN11.63 | length 2845.2
  Top Layer w10: R38.2@9788.9,4959.32 9788.9,4836.29 R42.2@9794.67,4830.52 ; R42.2@9790.13,4827.82 9790.13,4747.91 9807.17,4730.87 v1@10469.27,4730.87
  Bottom Layer w10: U1-CN11.63@10251.33,3410.37 10259.42,3410.37 10308.5,3459.45 10396.95,3459.45 10403.41,3465.91 10403.41,3560.91 10421.95,3579.45 10693.8,3579.45 10719.75,3605.4 10719.75,4678.45 10666.49,4731.72 v1@10471.8,4731.72
  other v1: 10470.32,4731.16
DIG15: R47.2 R51.2 U1-CN11.65 | length 2391.3
  Top Layer w10: R51.2@10341.25,4813.6 10341.25,4760.73 10342.22,4759.77 10645.1,4759.77 v1@10645.92,4758.95 ; R51.2@10345.18,4805.05 R47.2@10345.18,4947.31 ; U1-CN11.65@10348.46,3412.8 10432.81,3328.46 v1@10668.53,3328.46
  Bottom Layer w10: v1(10644.74,4760.1) 10676.56,4760.1 10740.18,4696.48 10740.18,3589.32 10708.17,3557.32 10685.65,3557.32 10665.2,3536.87 10665.2,3328.79 v1(10666.61,3327.38)
DIG16: R48.2 R52.2 U1-CN11.28 | length 1291.6
  Top Layer w10: R52.2@7598.11,3848.11 7598.11,3742.37 7617.85,3722.63 8439.66,3722.63 8456.41,3705.88 8456.41,3521.51 U1-CN11.28@8454.25,3519.34 ; R52.2@7602,3855.91 7606.85,3860.77 R48.2@7606.85,3978.88
DIG17: R49.2 R53.2 U1-CN11.32 | length 952
  Top Layer w10: R53.2@8154.31,3854.52 8157.46,3851.37 8157.46,3769.53 8186.36,3740.63 8639.96,3740.63 8661.01,3719.58 8661.01,3525.94 U1-CN11.32@8647.56,3512.48 ; R53.2@8156.75,3854.31 R49.2@8156.75,3983.11
DIG18: R50.2 R54.2 U1-CN11.38 | length 740.3
  Top Layer w10: R54.2@8656.56,3845.66 8662.33,3851.43 R50.2@8662.33,3980.22 ; R54.2@8661.81,3848.54 8665.57,3844.78 8665.57,3779.49 8687.02,3758.05 8924.69,3758.05 8946.48,3736.26 8946.48,3517.29 U1-CN11.38@8957.05,3506.72
DIG19: R57.2 R59.2 U1-CN11.40 | length 557.1
  Top Layer w10: U1-CN11.40@9048.58,3518.46 9058.19,3528.08 9058.19,3727.21 9090.08,3759.1 9158.78,3759.1 9181.22,3781.55 9181.22,3844.43 R59.2@9182.77,3845.98 ; R57.2@9178.48,3972.53 9178.48,3852.39 R59.2@9188.09,3842.77
DIG20: R58.2 R60.2 U1-CN11.42 | length 982.6
  Top Layer w10: U1-CN11.42@9154.55,3525.19 9156.71,3527.35 9156.71,3718.72 9176.83,3738.84 9691.15,3738.84 9710.13,3757.82 9710.13,3827.39 R60.2@9715.26,3832.52 ; R58.2@9714.81,3977.34 9714.81,3837.01 R60.2@9715.77,3836.05
DIG21: R62.2 R63.2 U1-CN11.44 | length 1460.9
  Top Layer w10: U1-CN11.44@9256.36,3501.68 9256.36,3701.03 9276.16,3720.83 10241.76,3720.83 10265.59,3744.66 10265.59,3836.17 R63.2@10264.15,3837.61 ; R62.2@10259.32,3976.86 10259.32,3837.49 R63.2@10260.28,3836.53
DO1: Q43.1 R74.2 U2-CN12.16 | length 4361
  Top Layer w10: Q43.1@4335.57,6788.43 4339.38,6784.61 R74.2@4339.38,6691.97 4339.38,6588.33 v1@4340.63,6587.08
  Bottom Layer w10: v1(4336.78,6585.16) 4336.78,6306.97 4368.8,6274.95 7837.06,6274.95 7855.27,6256.74 7855.27,5922.21 U2-CN12.16@7851.35,5918.29
DO2: Q44.1 R75.2 U2-CN12.18 | length 4197
  Top Layer w10: Q44.1@4586.22,6788.43 4593.96,6780.68 R75.2@4593.96,6691.97 ; v1@4594.38,6589.01 R75.2@4594.38,6685.12
  Bottom Layer w10: v1(4592.46,6589.01) 4592.46,6327.42 4626.93,6292.95 7931.42,6292.95 7954.98,6269.4 7954.98,5920.93 U2-CN12.18@7958.22,5917.69
DO3: Q45.1 R76.2 U2-CN12.22 | length 4156.8
  Top Layer w10: Q45.1@4840.82,6788.43 4848.56,6780.68 R76.2@4848.56,6691.97 4848.56,6594.24 v1@4847.17,6592.85
  Bottom Layer w10: v1(4849.09,6592.85) 4849.09,6337.59 4875.73,6310.95 8129.09,6310.95 8154.66,6285.38 8154.66,5918.59 U2-CN12.22@8160.43,5912.82
DO4: Q46.1 R77.2 U2-CN12.24 | length 4008.3
  Top Layer w10: Q46.1@5083.6,6788.43 5087.4,6784.62 R77.2@5087.4,6691.97 v1@5087.4,6587.14
  Bottom Layer w10: v1(5087.46,6583.24) 5087.46,6361.36 5119.88,6328.95 8227.6,6328.95 8252.34,6304.21 8252.34,5918.36 U2-CN12.24@8245.85,5911.87
DO5: Q47.1 R78.2 U2-CN12.26 | length 3864.6
  Top Layer w10: Q47.1@5338.19,6788.43 5342,6784.62 R78.2@5342,6691.97 5342,6585.34 v1@5342.17,6585.16
  Bottom Layer w10: v1(5341.21,6582.28) 5341.21,6365.29 5359.55,6346.95 8332.32,6346.95 8357.19,6322.08 U2-CN12.26@8357.19,5913.23
DO6: Q48.1 R89.2 U2-CN12.3 | length 2646.6
  Top Layer w10: Q48.1@5584.91,6788.43 5588.72,6784.62 R89.2@5588.72,6691.97 5588.72,6586.6 v1@5586.31,6584.2 ; U2-CN12.3@7246.31,5818.08 7272.26,5818.08 7302.54,5848.35 7302.54,6327.32 v1(7248.29,6381.57)
  Bottom Layer w10: v1(5587.27,6582.28) 5587.27,6468.75 5618.92,6437.1 7193.44,6437.1 7250.63,6379.91 v1@7250.63,6378.2
DO7: Q49.1 R90.2 U2-CN12.5 | length 2504
  Top Layer w10: Q49.1@5831.63,6788.43 5835.43,6784.62 R90.2@5835.43,6691.97 5835.43,6587.26 v1@5834.29,6586.12 ; U2-CN12.5@7349.94,5818.98 7374.45,5818.98 7401.84,5846.37 7401.84,6366.2 v1(7355.62,6412.42)
  Bottom Layer w10: v1(5832.37,6582.28) 5832.37,6484.63 5861.9,6455.1 7312.14,6455.1 v1@7355.7,6411.54
DO8: Q50.1 R91.2 U2-CN12.11 | length 2562.8
  Top Layer w10: Q50.1@6090.16,6788.43 6093.96,6784.62 R91.2@6093.96,6691.97 6093.96,6588.2 v1@6091.89,6586.12 ; U2-CN12.11@7662.44,5818.62 7663.08,5818.62 7704.25,5859.79 7704.25,6416.55 v1(7678.54,6442.26)
  Bottom Layer w10: v1(6089.01,6585.16) 6089.01,6492.86 6108.76,6473.1 7648.82,6473.1 7680.12,6441.8 v1@7680.12,6440.27
DO9: Q51.1 R92.2 U2-CN12.13 | length 2423.1
  Top Layer w10: v1@6329.3,6588.05 6329.3,6680.58 R92.2@6340.68,6691.97 6340.68,6784.62 Q51.1@6336.88,6788.43 ; v1(7752.51,6479.43) 7801.05,6430.89 7801.05,5857.55 7757.79,5814.29 U2-CN12.13@7757.79,5811.41
  Bottom Layer w10: v1(6329.3,6586.12) 6329.3,6509.66 6347.86,6491.1 7745.16,6491.1 v1@7752.51,6483.75
DO10: Q52.1 R93.2 U2-CN12.19 | length 2375.8
  Top Layer w10: Q52.1@6591.47,6788.43 6595.28,6784.62 R93.2@6595.28,6691.97 6595.28,6588.31 v1@6597.47,6586.12 ; v1(7850.64,6468.59) 7850.64,6072.75 7857.15,6066.24 8004.53,6066.24 8004.53,5856.06 U2-CN12.19@8049.38,5811.21
  Bottom Layer w10: v1(6596.51,6585.16) 6596.51,6521.3 6608.7,6509.1 7811.35,6509.1 7852.59,6467.87 v1@7852.59,6465.02
DO11: Q53.1 R104.2 U2-CN12.23 | length 4950.6
  Top Layer w10: Q53.1@4296.2,5548.27 4303.94,5540.53 R104.2@4303.94,5428.19 ; v1@4301.25,5328.13 4302.21,5329.09 R104.2@4302.21,5429.05 ; v1(8207.14,5702.24) 8244.15,5702.24 8256.65,5714.73 U2-CN12.23@8256.65,5804.12
  Bottom Layer w10: v1(4300.2,5328.48) 4300.2,5176.63 4340.68,5136.16 8084.33,5136.16 8207.16,5258.98 v1@8207.16,5702.22 ; U2-CN12.23@8256.4,5804.99 U2-CN12.23@8265.05,5813.64
DO12: Q54.1 R105.2 U2-CN12.25 | length 4763.2
  Top Layer w10: Q54.1@4542.92,5548.27 4549.32,5541.86 R105.2@4549.32,5428.19 ; v1@4549.23,5323.32 4550.19,5324.28 R105.2@4550.19,5429.05 ; v1(8176.59,5676.57) 8333.95,5676.57 8348.92,5691.53 U2-CN12.25@8348.92,5806.04
  Bottom Layer w10: v1(4550.51,5323.8) 4550.51,5181.53 4577.89,5154.16 8072.85,5154.16 8176.59,5257.9 v1(8176.59,5676.57)
DO13: Q55.1 R106.2 U2-CN12.27 | length 4594.6
  Top Layer w10: Q55.1@4797.51,5548.27 4802.58,5543.19 R106.2@4802.58,5428.19 ; v1@4800.74,5323.64 4801.06,5323.96 R106.2@4801.06,5425.21 ; v1(8144.77,5650.9) 8145.43,5651.56 8435.81,5651.56 8455.61,5671.36 U2-CN12.27@8455.61,5800.27 ; U2-CN12.27@8450.17,5811.59 U2-CN12.27@8454.01,5807.75
  Bottom Layer w10: v1(4802.34,5322.52) 4802.34,5179.51 4809.7,5172.16 8058.39,5172.16 8145.25,5259.02 8145.25,5650.41 v1(8144.77,5650.9)
DO14: Q56.1 R107.2 U2-CN12.37 | length 4805.3
  Top Layer w10: Q56.1@5056.04,5548.27 5059.78,5544.52 R107.2@5059.78,5428.19 ; v1@5057.05,5321.4 R107.2@5057.05,5429.69 ; v1(8115.19,5625.23) 8115.78,5625.82 8925.81,5625.82 8951.09,5651.1 U2-CN12.37@8951.09,5814.21
  Bottom Layer w10: v1(5057.37,5321.24) 5057.37,5211.61 5078.83,5190.16 8037.09,5190.16 8115.23,5268.3 v1(8115.19,5625.23)
DO15: Q57.1 R108.2 U2-CN12.41 | length 4732
  Top Layer w10: Q57.1@5306.69,5548.27 5309.11,5545.86 R108.2@5309.11,5428.19 ; R108.2@5308.24,5426.49 5308.24,5322.68 v1@5309.52,5321.4 ; v1(8087.85,5599.56) 9129.98,5599.56 9154.56,5624.14 9154.56,5812.71 U2-CN12.41@9150.23,5817.04
  Bottom Layer w10: v1(5308.56,5321.24) 5307.18,5319.86 5307.18,5230.1 5329.13,5208.16 ; 5329.29,5208.16 8021.34,5208.16 8087.85,5274.66 v1(8087.85,5599.56)
DO16: Q58.1 R119.2 U2-CN12.43 | length 4543.2
  Top Layer w10: v1@5556.86,5320.12 R119.2@5556.86,5426.49 ; Q58.1@5557.35,5548.27 5558.43,5547.19 R119.2@5558.43,5428.19 ; v1(8060.72,5573.89) 9230.65,5573.89 9254.12,5597.36 9254.12,5803.58 U2-CN12.43@9253.16,5804.54
  Bottom Layer w10: v1(5555.9,5323.16) 5555.9,5244.04 5573.79,5226.16 8001.85,5226.16 8061.9,5286.2 8061.9,5572.71 v1(8060.72,5573.89)
DO17: Q59.1 R120.2 U2-CN12.45 | length 4373.6
  Top Layer w10: R120.2@5807.75,5428.19 5807.75,5548.01 Q59.1@5808.01,5548.27 ; v1@5808.69,5321.4 R120.2@5808.69,5425.21 ; v1(8031.46,5548.22) 9327.71,5548.22 9352.99,5573.5 9352.99,5810.2 U2-CN12.45@9342.58,5820.62
  Bottom Layer w10: v1(5809.01,5323.8) 5809.01,5263.04 5827.89,5244.16 7982.15,5244.16 8031.46,5293.46 v1(8031.46,5548.22)
DO18: Q60.1 R121.2 U2-CN12.47 | length 4192.2
  Top Layer w10: R121.2@6061.01,5428.19 6061.01,5546.68 Q60.1@6062.6,5548.27 ; v1@6063.08,5322.68 6063.72,5323.32 R121.2@6063.72,5430.98 ; v1(8003.26,5522.55) 8003.92,5523.21 9429.56,5523.21 9453.68,5547.33 9453.68,5811.15 U2-CN12.47@9454.97,5812.43 ; U2-CN12.47@9453.46,5816.82 U2-CN12.47@9454.1,5816.18
  Bottom Layer w10: v1(6058.92,5324.44) 6058.92,5278.43 6075.19,5262.16 7964.91,5262.16 8004.11,5301.36 8004.11,5521.7 v1(8003.26,5522.55)
DO19: Q61.1 R122.2 U2-CN12.49 | length 3997.4
  Top Layer w10: R122.2@6306.4,5428.19 6306.4,5545.35 Q61.1@6309.32,5548.27 ; v1@6306.58,5324.61 R122.2@6306.58,5425.85 ; v1(7972.29,5496.88) 7972.95,5497.54 9527.65,5497.54 9555.17,5525.06 9555.17,5791.95 U2-CN12.49@9543.63,5803.48
  Bottom Layer w10: v1(6307.54,5323.16) 6307.54,5291.56 6318.94,5280.16 7936.99,5280.16 7971.73,5314.9 7971.73,5496.32 v1(7972.29,5496.88)
DO20: Q62.1 R123.2 U2-CN12.51 | length 3808.7
  Top Layer w10: v1@6559.66,5323.35 R123.2@6559.66,5428.19 6563.91,5432.44 Q62.1@6563.91,5548.27 ; v1(7944.1,5471.21) 7944.76,5471.87 9625.74,5471.87 9654.78,5500.91 9654.78,5794.11 U2-CN12.51@9661.99,5801.32 ; U2-CN12.51@9651.06,5804.97 U2-CN12.51@9653.94,5802.09
  Bottom Layer w10: v1(6558.73,5320.6) 6581.17,5298.16 7915.15,5298.16 7945.04,5328.05 7945.04,5470.27 v1(7944.1,5471.21)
